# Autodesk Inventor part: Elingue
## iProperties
Shininess: 64.0
Length Units: 11269
Angle Units: 11279
Time Units: 11290
Mass Units: 11283
Length Display Precision: 3
Angle Display Precision: 2
Compacted: True
Part Number: Elingue
Document SubType Name: Modeling
Created: 2008-04
Material: Par défaut
Designer: Pascal
Density: 0.0
Volumn: 0.0
Area: 0.0
PropertySet Name: Model Information
Control State: 0
Master: False
Checked Out: False
DESIGNATION: pièce
Author: Pascal
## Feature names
1. Balayage1
2. Balayage2
3. Symétrie1 [Mirror]
